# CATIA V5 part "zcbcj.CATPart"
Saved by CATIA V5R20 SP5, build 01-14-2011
Part number: zcbcj
Bounding box of the stored display mesh (mm): x -100 to 100, y -99.994 to 99.994, z -2.5 to 22.218
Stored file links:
  E:\180222112\zcbcj.CATPart
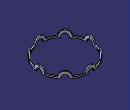
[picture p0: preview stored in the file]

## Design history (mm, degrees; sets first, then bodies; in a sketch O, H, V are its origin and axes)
Body1 (main body)
  Sketch1 on xy-plane, origin (0, 0, 0), H (1, 0, 0), V (0, 1, 0)
    circle A1 centre (0, 0) radius 100
    point P1 (100, 0)
    radius A1 = 100
    coincidence: A1 P1, P1 H
  Pad1: profile Sketch1, direction (0, 0, 1), length 2.5, mirrored extent, thin wall 5
  Body2
    Sketch2 on xy-plane, origin (0, 0, 0), H (1, 0, 0), V (0, 1, 0)
      arc A1 centre (99.7611, 0) radius 20 from (97.5, -19.8718) to (97.5, 19.8718) ccw
      point P1 (99.7611, 0)
      axis line L1 (97.5, 58.7204) -> (97.5, -69.3375)
      point P4 (97.5, 19.8718)
      point P5 (97.5, -19.8718)
      radius A1 = 20
      distance O L1 = 97.5
      coincidence: P1 H, L1 P4, L1 P5
      vertical: L1 V
    Shaft1: profile Sketch2, axis Sketch2.L1, angle 360
    CircPattern1: of the body so far, instances 8, angular step 45, axis from end face of Pad1
    Sketch3 on xy-plane, origin (0, 0, 0), H (1, 0, 0), V (0, 1, 0)
      circle A1 centre (0, 0) radius 95
      radius A1 = 95
    Pocket1: profile Sketch3, direction (0, 0, -1), length 60, mirrored extent
    Split1: SplitPlane start face of Pad1
    Sketch4 on xy-plane, origin (0, 0, 0), H (1, 0, 0), V (0, 1, 0)
      circle A1 centre (0, 0) radius 100
      radius A1 = 100
    Pocket2: profile Sketch4, direction (0, 0, -1), length 60, mirrored extent, outer side
  Assemble1: tool Body2
  Body3
    Plane1: type Offset, RefPlane yz-plane, Offset 97.5
    Sketch5 on Plane1, origin (97.5, 0, 0), H (0, 1, 0), V (0, 0, 1)
      arc A1 centre (0, 0) radius 12 from (-12, 0) to (12, 0) ccw
      axis line L1 (120.8326, 0) -> (-154.9399, 0)
      point P1 (120.8326, 0)
      point P3 (-12, 0)
      point P4 (12, 0)
      radius A1 = 12
      coincidence: P1 H, L1 P4, L1 P3
      horizontal: L1 H
    Shaft2: profile Sketch5, axis Sketch5.L1, angle 360
    CircPattern2: of the body so far, instances 8, angular step 45, axis from face of Pad1
    Sketch6 on xy-plane, origin (0, 0, 0), H (1, 0, 0), V (0, 1, 0)
      circle A1 centre (0, 0) radius 100
      radius A1 = 100
  Remove1: tool Body3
